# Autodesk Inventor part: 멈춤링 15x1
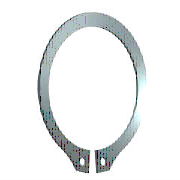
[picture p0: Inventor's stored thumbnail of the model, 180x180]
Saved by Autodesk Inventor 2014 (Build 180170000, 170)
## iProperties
Created: 2015-09
Part Number: 멈춤링 15x1
Material: 강철, 연강
Description: 리테이닝 링(C형)
Document SubType Name: Modeling
Standard: KS B 1336
Designer: mm
Standards Organization: KS
Language: ko-KR
Size Designation: 15 x 1
Categories: <MemberInstance><Categories><Category DisplayName="샤프트 부품" InternalName="7f7aeb1f-a693-4053-b835-cee3144e0d98" Mnemonic="SHFT"><Category DisplayName="써클립" Inter
Density: 1 g/cm^3
Appearance: Blue - Wall Paint - Glossy
IsCustomPart: 1
Author: mduedu
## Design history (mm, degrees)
sketch "스케치1"
  geometry: L1 (-6, 0)-(6, 0) reference; L2 (0, 20.189)-(0, -80.536) reference; L3 (-48.09, 0)-(48.09, 0) reference; L4 (-0.425, -14.637)-(-0.425, -18.137); L5 (-0.425, -6.54)-(-0.425, -13.29); L6 (-2.795, 2.1)-(3.672, 2.1); L7 (0.425, -6.54)-(0.425, -13.29); L8 (0.425, -14.637)-(0.425, -18.137); C1 r 0.85 at (-1.7, -16.283); C2 r 0.85 at (1.7, -16.283); A1 r 7.15 centre (0, -7.5) between (0.425, -14.637) and (-0.425, -14.637); A2 r 9.075 centre (0, -6.975) between (4.291, -14.971) and (-4.291, -14.971); A3 r 10.646 centre (0, -7.5) between (-2.023, -17.952) and (-0.425, -18.137); A4 r 1.7 centre (-1.7, -16.283) between (-3.397, -16.376) and (-2.023, -17.952); A5 r 1.7 centre (-5.095, -16.469) between (-3.397, -16.376) and (-4.291, -14.971); A6 r 1.7 centre (5.095, -16.469) between (4.291, -14.971) and (3.397, -16.376); A7 r 1.7 centre (1.7, -16.283) between (2.023, -17.952) and (3.397, -16.376); A8 r 10.646 centre (0, -7.5) between (0.425, -18.137) and (2.023, -17.952)
  constraints: 16 point on circle, 12 end point, 10 centre point, 9 symmetric about line, 5 point on line, 4 tangent, 3 coincident, 2 horizontal, 1 perpendicular, 1 vertical, 5 other
  dimensions: "d0" = 14.3 diameter of A1 (= ND); "d1" = 3.5 distance of L4.end L4.start (= SRB2); "d6" = 0.425 distance between parallel lines of L2 L5 (= 0.25 x SD5); "d7" = 2.1 distance between parallel lines of L6 L3 (= SRB1); "d8" = 0.525 distance of A1.centre A2.centre (= 0.25 x SRB1); "d9" = 1.7 radius of A4 (= SD5); "d10" = 1.7 radius of A5 (= SD5); "d11" = 1.275 distance from line of L4 A4.centre (= 0.75 x SD5); "d12" = 1.7 diameter of C1 (= SD5); "d13" = 1.7 diameter of C2 (= SD5); "d14" = 7.5 distance from line of A1.centre L1 (= 0.5 x WD)
extrude "본체" new body sketch "스케치1" distance "d2" = 1 (= SD); taper "d3" = 0 deg
workaxis "Work Axis1"
workplane "Work Plane1"
body "Solid1"
other parameters: "WD" = 15 (= WDMIN) [user parameter; used in 1 equation term], "SD" = 1 [user parameter; used in 1 equation term], "SRB1" = 2.1 [user parameter; used in 2 equation terms], "ND" = 14.3 [user parameter; used in 1 equation term], "SRB2" = 3.5 [user parameter; used in 1 equation term], "SD5" = 1.7 [user parameter; used in 6 equation terms], "d15" = 0, "d16" = 0, "d17" = 0, "d41" = 0, "d42" = 0, "WDMIN" = 15 [user parameter; used in 1 equation term], "SD3" = 13.8 [user parameter], "WDMAX" = 16 [user parameter]
